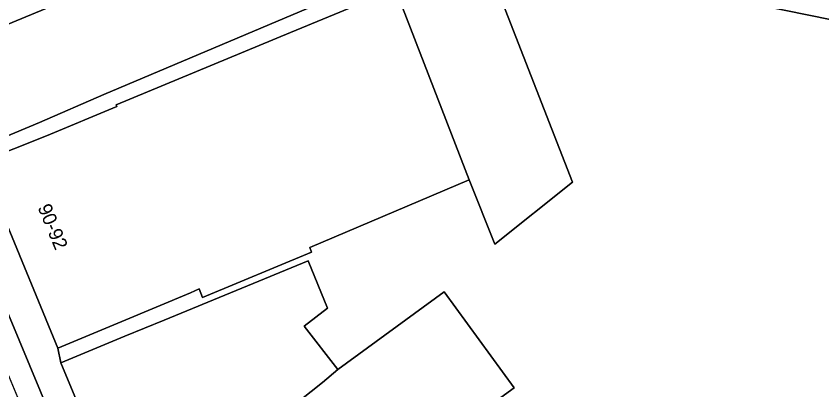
# Model space of a CAD drawing. Extents: x 159716 to 160783, y 383290 to 384031.
# Drawn here: x 159971.7 to 160030, y 383331.4 to 383358.4 of the extents above; entities that cross this region are included whole.
import ezdxf

# ---------------------------------------------------------------- set-up
doc = ezdxf.new("R2010")
doc.units = 0
for name, color, linetype in [('IMGEO_Erf', 7, 'Continuous'), ('IMGEO_Pand', 7, 'Continuous'), ('IMGEO_Pand_nummerreeks', 7, 'Continuous'), ('IMGEO_Parkeervlak_open', 7, 'Continuous'), ('IMGEO_Voetpad_open', 7, 'Continuous')]:
    doc.layers.add(name, color=color, linetype=linetype)

msp = doc.modelspace()

# ---------------------------------------------------------------- linework, layer by layer
at = {"layer": 'IMGEO_Erf'}
for points in [[(160006.368, 383360.79), (160011.959, 383346.418), (160006.342, 383341.94), (160004.483, 383346.591), (160000, 383344.687), (159992.949, 383341.692), (159993.088, 383341.356), (159985.204, 383338.089), (159984.945, 383338.714), (159984.325, 383338.409), (159979.36, 383336.346), (159974.74, 383334.431), (159974.956, 383333.37), (159979.576, 383335.285), (159982.413, 383336.451), (159992.839, 383340.736), (159994.244, 383337.317), (159992.557, 383336), (159994.989, 383332.888), (160002.683, 383338.49), (160007.736, 383331.548), (160000.251, 383326.099)], [(160084.319, 383348.085), (160082.606, 383348.26), (160067.307, 383350.441), (160066.853, 383347.225), (160060.486, 383348.123), (160060.899, 383351.046), (160050.946, 383352.451), (160051.165, 383354.007), (160022.158, 383359.914)]]:
    msp.add_lwpolyline(points, dxfattribs=at)
at = {"layer": 'IMGEO_Pand'}
for points in [[(159991.124, 383358.291), (159998.545, 383361.437), (159997.63, 383363.725), (159995.875, 383368.116), (159984.752, 383363.502), (159965.918, 383355.69), (159968.777, 383348.817), (159973.398, 383350.731), (159978.066, 383352.755)], [(159974.627, 383366.728), (159963.258, 383362.084), (159965.918, 383355.69), (159984.752, 383363.502), (159983.673, 383366.103), (159978.122, 383363.801), (159978.253, 383363.483), (159976.292, 383362.669)], [(160002.231, 383361.493), (160001.715, 383361.589), (159998.929, 383360.476), (159998.99, 383360.32), (159999.154, 383360.388), (159999.958, 383358.306), (160004.483, 383346.591), (160006.342, 383341.94), (160011.959, 383346.418), (160006.368, 383360.79), (160005.183, 383360.991)], [(160004.483, 383346.591), (159999.958, 383358.306), (159999.154, 383360.388), (159998.99, 383360.32), (159991.559, 383357.241), (159978.941, 383352.013), (159978.995, 383351.883), (159973.922, 383349.78), (159969.165, 383347.884), (159974.74, 383334.431), (159979.36, 383336.346), (159984.325, 383338.409), (159984.945, 383338.714), (159985.204, 383338.089), (159993.088, 383341.356), (159992.949, 383341.692), (160000, 383344.687)], [(159994.989, 383332.888), (159992.557, 383336), (159994.244, 383337.317), (159992.839, 383340.736), (159982.413, 383336.451), (159979.576, 383335.285), (159974.956, 383333.37), (159977.932, 383326.175), (159980.025, 383321.114), (159980.078, 383320.999), (159993.871, 383331.942)], [(160000, 383321.412), (160002.477, 383323.348), (160000.251, 383326.099), (160007.736, 383331.548), (160002.683, 383338.49), (159994.989, 383332.888), (159993.871, 383331.942), (159980.078, 383320.999), (159985.228, 383309.868), (159989.169, 383312.946)]]:
    msp.add_lwpolyline(points, close=True, dxfattribs=at)
at = {"layer": 'IMGEO_Parkeervlak_open'}
msp.add_lwpolyline([(159948.812, 383386.157), (159949.871, 383383.505), (159949.966, 383383.258), (159955.108, 383370.858), (159961.153, 383356.412), (159965.645, 383345.705), (159970.733, 383333.492), (159973.369, 383327.119), (159974.802, 383324.048), (159977.454, 383318.733), (159982.131, 383309.478), (159983.697, 383310.309), (159980.808, 383315.928), (159978.449, 383320.528), (159976.306, 383324.84), (159975.031, 383327.576), (159958.266, 383367.838), (159956.81, 383371.336), (159951.4, 383384.328)], dxfattribs=at)
at = {"layer": 'IMGEO_Voetpad_open'}
for points in [[(159951.4, 383384.328), (159956.81, 383371.336), (159957.77, 383371.736), (159959.226, 383368.238), (159958.266, 383367.838), (159975.031, 383327.576), (159976.306, 383324.84), (159978.449, 383320.528), (159979.374, 383321.003), (159981.733, 383316.403), (159980.808, 383315.928), (159983.697, 383310.309), (159982.131, 383309.478), (159982.341, 383309.117), (159983.27, 383309.584), (159985.999, 383304.155), (159985.07, 383303.688), (159985.742, 383302.367), (159986.718, 383300.546), (159987.343, 383299.335), (159996.044, 383298.242)], [(160022.158, 383359.914), (160051.165, 383354.007), (160050.946, 383352.451), (160060.899, 383351.046), (160060.94, 383351.34), (160067.307, 383350.441), (160082.606, 383348.26), (160082.957, 383349.761), (160080.935, 383350.046), (160077.023, 383350.598), (160073.116, 383351.149), (160069.492, 383351.503), (160065.75, 383351.969), (160061.913, 383352.447), (160061.941, 383352.67), (160060.074, 383352.903), (160056.135, 383353.425), (160052.534, 383353.901), (160055.073, 383373.551)], [(159986.866, 383307.586), (159985.228, 383309.868), (159980.078, 383320.999), (159980.025, 383321.114), (159977.932, 383326.175), (159974.956, 383333.37), (159974.74, 383334.431), (159969.165, 383347.884)]]:
    msp.add_lwpolyline(points, dxfattribs=at)
msp.add_lwpolyline([(159991.559, 383357.241), (159998.99, 383360.32), (159998.929, 383360.476), (159998.545, 383361.437), (159991.124, 383358.291), (159978.066, 383352.755), (159973.398, 383350.731), (159968.777, 383348.817), (159969.165, 383347.884), (159973.922, 383349.78), (159978.995, 383351.883), (159978.941, 383352.013)], close=True, dxfattribs=at)

# ---------------------------------------------------------------- texts
at = {"layer": 'IMGEO_Pand_nummerreeks'}
msp.add_text('90-92', height=1, rotation=292.5113, dxfattribs=at).set_placement((159973.255, 383344.597))

doc.saveas('drawing.dxf')
